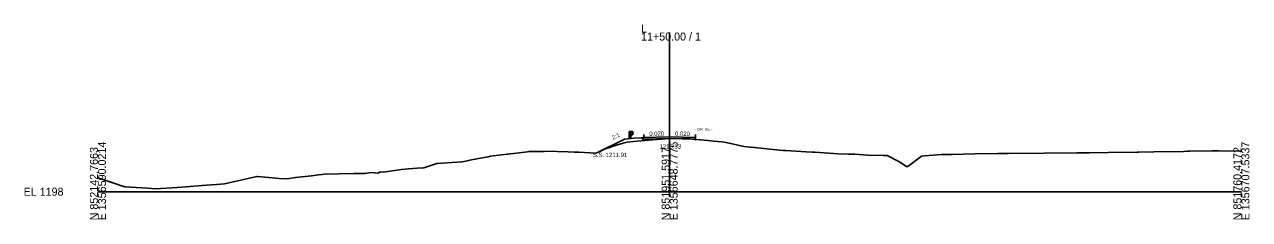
# Model space of a CAD drawing. Extents: x -26 to 3203, y -10 to 4066.
# Drawn here: x -25.7 to 402.8, y 990.3 to 1058.4 of the extents above; entities that cross this region are included whole.
import ezdxf

# ---------------------------------------------------------------- set-up
doc = ezdxf.new("R2010")
doc.units = 0
for name, color, linetype in [('Exist Cross Section Cell', 7, 'Continuous'), ('Exist XS Center Line Elevation Label', 7, 'Continuous'), ('Exist XS Ground Line', 7, 'Continuous'), ('Prop XS Dump Level', 7, 'Continuous'), ('Prop XS Earthwork Shape', 7, 'Continuous'), ('Prop XS EOT Tick Mark', 7, 'Continuous'), ('Prop XS Finish Grade', 7, 'Continuous'), ('Prop XS Finish Grade Earthwork', 7, 'Continuous'), ('Prop XS Finish Grade Pavement', 7, 'Continuous'), ('Prop XS Guardrail', 7, 'Continuous'), ('Prop XS Pvmt Edge Slope', 7, 'Continuous'), ('Prop XS SE Text', 7, 'Continuous'), ('Prop XS Side Slope Text', 7, 'Continuous'), ('Prop XS SS Elevation Text', 7, 'Continuous'), ('Prop XS Subgrade Earthwork', 7, 'Continuous'), ('Prop XS Vertical Lines', 7, 'Continuous')]:
    doc.layers.add(name, color=color, linetype=linetype)

msp = doc.modelspace()

# ---------------------------------------------------------------- linework, layer by layer
at = {"layer": 'Exist Cross Section Cell'}
for p, q in [((200, 1000), (200, 1055.6)), ((0, 1000), (200, 1000)), ((200, 1000), (400, 1000))]:
    msp.add_line(p, q, dxfattribs=at)
at = {"layer": 'Exist XS Ground Line'}
for p, q in [((178.68, 1015.27), (180.25, 1015.96)), ((180.25, 1015.96), (183.73, 1016.92)), ((183.73, 1016.92), (185.13, 1017.31)), ((185.13, 1017.31), (187.39, 1017.52)), ((187.39, 1017.52), (192.56, 1018.06)), ((192.56, 1018.06), (197.17, 1018.3)), ((197.17, 1018.3), (200.07, 1018.53)), ((200.07, 1018.53), (205.6, 1018.46)), ((205.6, 1018.46), (207.26, 1018.44)), ((207.26, 1018.44), (208.65, 1018.24)), ((208.65, 1018.24), (210.73, 1018.11)), ((210.73, 1018.11), (212.09, 1017.98)), ((212.09, 1017.98), (213.38, 1017.89)), ((213.38, 1017.89), (215.18, 1017.7)), ((215.18, 1017.7), (218.22, 1017.41)), ((218.22, 1017.41), (219.71, 1017.2)), ((219.71, 1017.2), (225.99, 1015.85)), ((225.99, 1015.85), (228.22, 1015.6)), ((130.09, 1011.05), (133.14, 1011.57)), ((133.14, 1011.57), (136.5, 1012.23)), ((136.5, 1012.23), (137.37, 1012.38)), ((137.37, 1012.38), (143.1, 1013.06)), ((143.1, 1013.06), (143.44, 1013.12)), ((143.44, 1013.12), (150.27, 1013.97)), ((150.27, 1013.97), (150.76, 1014.01)), ((150.76, 1014.01), (156.06, 1014.05)), ((156.06, 1014.05), (156.92, 1014.12)), ((156.92, 1014.12), (164.46, 1013.94)), ((164.46, 1013.94), (166.75, 1013.85)), ((166.75, 1013.85), (167.27, 1013.83)), ((167.27, 1013.83), (168.18, 1013.78)), ((168.18, 1013.78), (174.21, 1013.49)), ((174.21, 1013.49), (175.34, 1013.95)), ((175.34, 1013.95), (177.47, 1014.93)), ((177.47, 1014.93), (178.68, 1015.27)), ((228.22, 1015.6), (229.63, 1015.49)), ((229.63, 1015.49), (238.38, 1014.54)), ((238.38, 1014.54), (239.74, 1014.45)), ((239.74, 1014.45), (240.68, 1014.39)), ((240.68, 1014.39), (247.7, 1013.94)), ((247.7, 1013.94), (249.9, 1013.8)), ((249.9, 1013.8), (250.73, 1013.76)), ((250.73, 1013.76), (258.89, 1013.24)), ((258.89, 1013.24), (262.58, 1013.17)), ((262.58, 1013.17), (264.74, 1013.06)), ((264.74, 1013.06), (269.34, 1012.77)), ((269.34, 1012.77), (274.65, 1012.63)), ((274.65, 1012.63), (276.07, 1012.63)), ((276.07, 1012.63), (280.38, 1010.4)), ((283.83, 1009.19), (288.06, 1012.36)), ((288.06, 1012.36), (289.17, 1012.51)), ((289.17, 1012.51), (295.15, 1013)), ((295.15, 1013), (298.34, 1013.03)), ((298.34, 1013.03), (298.82, 1013.04)), ((298.82, 1013.04), (306.75, 1013.21)), ((306.75, 1013.21), (314.82, 1013.32)), ((314.82, 1013.32), (318.42, 1013.34)), ((318.42, 1013.34), (331.01, 1013.42)), ((331.01, 1013.42), (342.46, 1013.58)), ((342.46, 1013.58), (346.92, 1013.6)), ((346.92, 1013.6), (353.34, 1013.65)), ((353.34, 1013.65), (363.57, 1013.8)), ((363.57, 1013.8), (364.08, 1013.81)), ((364.08, 1013.81), (369.33, 1013.9)), ((369.33, 1013.9), (379.78, 1014.08)), ((379.78, 1014.08), (381.25, 1014.11)), ((381.25, 1014.11), (381.97, 1014.12)), ((381.97, 1014.12), (389.68, 1014.24)), ((389.68, 1014.24), (391.94, 1014.27)), ((391.94, 1014.27), (400, 1014.13)), ((99.78, 1006.82), (106.2, 1007.75)), ((106.2, 1007.75), (108.64, 1007.98)), ((108.64, 1007.98), (111.65, 1008.24)), ((111.65, 1008.24), (113.99, 1008.38)), ((113.99, 1008.38), (118.5, 1009.85)), ((118.5, 1009.85), (120.53, 1009.95)), ((120.53, 1009.95), (127.33, 1010.44)), ((127.33, 1010.44), (128.04, 1010.5)), ((128.04, 1010.5), (128.71, 1010.67)), ((128.71, 1010.67), (130.09, 1011.05)), ((280.38, 1010.4), (282.96, 1008.74)), ((282.96, 1008.74), (283.83, 1009.19)), ((0, 1004.89), (6.99, 1002.5)), ((44.28, 1002.77), (55.55, 1005.29)), ((55.55, 1005.29), (55.9, 1005.36)), ((55.9, 1005.36), (63.36, 1004.61)), ((63.36, 1004.61), (66.14, 1004.51)), ((66.14, 1004.51), (69.08, 1004.92)), ((69.08, 1004.92), (74.71, 1005.55)), ((74.71, 1005.55), (77.14, 1005.86)), ((77.14, 1005.86), (78.36, 1006)), ((78.36, 1006), (79.09, 1006.08)), ((79.09, 1006.08), (89.66, 1006.32)), ((89.66, 1006.32), (93.44, 1006.39)), ((93.44, 1006.39), (95.3, 1006.67)), ((95.3, 1006.67), (97.95, 1006.53)), ((97.95, 1006.53), (98.82, 1006.91)), ((98.82, 1006.91), (99.78, 1006.82)), ((6.99, 1002.5), (7.5, 1002.23)), ((7.5, 1002.23), (9.37, 1001.69)), ((9.37, 1001.69), (17.29, 1001.21)), ((17.29, 1001.21), (20.12, 1001.03)), ((20.12, 1001.03), (27.76, 1001.52)), ((27.76, 1001.52), (38.03, 1002.3)), ((38.03, 1002.3), (41.49, 1002.54)), ((41.49, 1002.54), (44.28, 1002.77))]:
    msp.add_line(p, q, dxfattribs=at)
at = {"layer": 'Prop XS Dump Level'}
for p, q in [((191, 1018.94), (200, 1019.12)), ((200, 1019.12), (209, 1018.94))]:
    msp.add_line(p, q, dxfattribs=at)
at = {"layer": 'Prop XS Earthwork Shape'}
for points in [[(206.42, 1018.45), (200, 1018.58), (191, 1018.4), (190.45, 1018.39), (189.98, 1018.86), (187.42, 1018.65), (184.21, 1018.4), (175.23, 1013.91), (175.34, 1013.95), (177.47, 1014.93), (178.68, 1015.27), (180.25, 1015.96), (183.73, 1016.92), (185.13, 1017.31), (187.39, 1017.52), (192.56, 1018.06), (197.17, 1018.3), (200.07, 1018.53), (205.6, 1018.46)], [(207.31, 1018.43), (206.42, 1018.45), (207.26, 1018.44)], [(207.31, 1018.43), (208.65, 1018.24), (209, 1018.22), (209, 1018.4)]]:
    msp.add_lwpolyline(points, close=True, dxfattribs=at)
at = {"layer": 'Prop XS EOT Tick Mark'}
for p, q in [((191, 1018.94), (191, 1019.94)), ((209, 1018.94), (209, 1019.94))]:
    msp.add_line(p, q, dxfattribs=at)
at = {"layer": 'Prop XS Finish Grade'}
for p, q in [((191, 1018.94), (189.98, 1018.86)), ((209, 1018.94), (209, 1018.4))]:
    msp.add_line(p, q, dxfattribs=at)
at = {"layer": 'Prop XS Finish Grade Earthwork'}
for p, q in [((184.21, 1018.4), (175.23, 1013.91)), ((187.42, 1018.65), (184.21, 1018.4)), ((189.98, 1018.86), (187.42, 1018.65)), ((209, 1018.4), (209, 1018.22))]:
    msp.add_line(p, q, dxfattribs=at)
at = {"layer": 'Prop XS Finish Grade Pavement'}
for p, q in [((191, 1018.94), (200, 1019.12)), ((200, 1019.12), (209, 1018.94))]:
    msp.add_line(p, q, dxfattribs=at)
at = {"layer": 'Prop XS Guardrail'}
for p, q in [((185.89, 1021.03), (186.39, 1021.03)), ((185.89, 1018.53), (185.89, 1021.03)), ((186.39, 1021.03), (186.89, 1021.03)), ((186.39, 1021.03), (186.39, 1018.53)), ((186.89, 1021.03), (187.18, 1020.83)), ((187.18, 1020.71), (186.89, 1020.51)), ((186.89, 1020.51), (186.89, 1020.42)), ((186.89, 1020.42), (187.18, 1020.22)), ((187.18, 1020.1), (186.89, 1019.9)), ((187.18, 1020.83), (187.21, 1020.77)), ((187.21, 1020.77), (187.18, 1020.71)), ((187.18, 1020.22), (187.21, 1020.16)), ((187.21, 1020.16), (187.18, 1020.1)), ((186.89, 1019.9), (186.39, 1019.9))]:
    msp.add_line(p, q, dxfattribs=at)
at = {"layer": 'Prop XS Pvmt Edge Slope'}
msp.add_line((191, 1018.94), (190.45, 1018.39), dxfattribs=at)
at = {"layer": 'Prop XS Subgrade Earthwork'}
for p, q in [((190.45, 1018.39), (189.98, 1018.86)), ((191, 1018.4), (190.45, 1018.39)), ((200, 1018.58), (191, 1018.4)), ((209, 1018.4), (200, 1018.58))]:
    msp.add_line(p, q, dxfattribs=at)
at = {"layer": 'Prop XS Vertical Lines'}
msp.add_line((209, 1019.94), (209, 1018.05), dxfattribs=at)

# ---------------------------------------------------------------- texts
at = {"layer": 'Exist Cross Section Cell'}
for s, p in [('11+50.00 / 1', (190, 1052.8)), ('L', (190, 1055.6)), ('EL 1198', (-26, 998.6))]:
    msp.add_text(s, height=2.8, dxfattribs=at).set_placement(p)
for s, p in [('E 1356590.0214', (2.8, 990)), ('E 1356648.7775', (202.8, 990)), ('E 1356707.5337', (402.8, 990)), ('N 852142.7663', (0, 990)), ('N 851951.5917', (200, 990)), ('N 851760.4172', (400, 990))]:
    msp.add_text(s, height=2.8, rotation=90, dxfattribs=at).set_placement(p)
at = {"layer": 'Exist XS Center Line Elevation Label'}
msp.add_text('1216.53', height=1.5, dxfattribs=at).set_placement((196.49, 1015.07))
at = {"layer": 'Prop XS Dump Level'}
msp.add_text('Case1', height=0.04, dxfattribs=at).set_placement((187.42, 1018.61))
at = {"layer": 'Prop XS SE Text'}
for rotation, p in [(1.1458, (192.88, 1019.48)), (358.8542, (201.88, 1019.58))]:
    msp.add_text('0.020', height=1.5, rotation=rotation, dxfattribs=at).set_placement(p)
at = {"layer": 'Prop XS Side Slope Text'}
msp.add_text('2:1', height=1.5, rotation=26.5651, dxfattribs=at).set_placement((180.21, 1018.07))
at = {"layer": 'Prop XS SS Elevation Text'}
msp.add_text('S.S. 1211.91', height=1.5, dxfattribs=at).set_placement((173.16, 1012.11))
at = {"layer": 'Prop XS Vertical Lines'}
msp.add_text('- DR TIE -', height=1, dxfattribs=at).set_placement((208.75, 1021.31))

doc.saveas('drawing.dxf')
